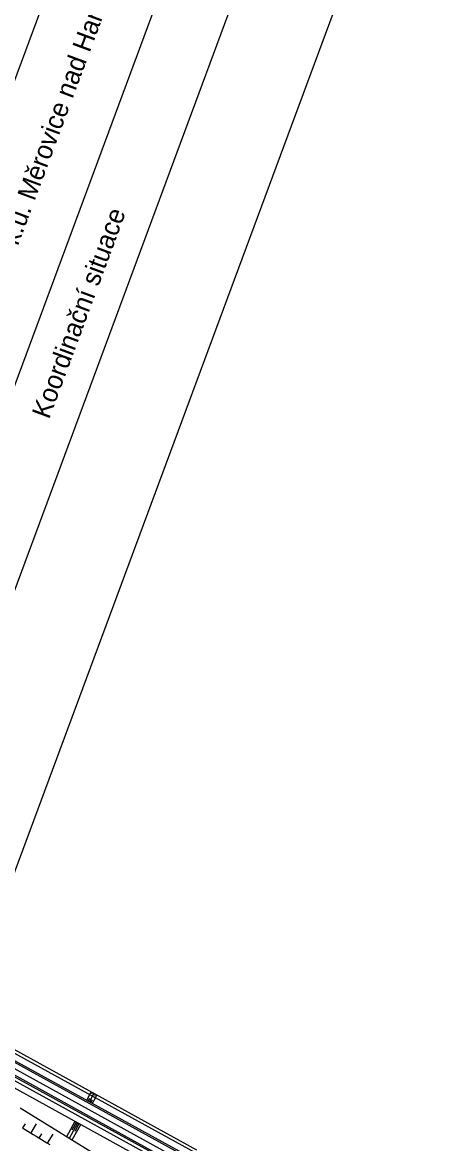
# Model space of a CAD drawing. Extents: x -552278 to -547230, y -1151007 to -1148251.
# Drawn here: x -550305.8 to -550177.8, y -1149028.3 to -1148678 of the extents above; entities that cross this region are included whole.
import ezdxf

# ---------------------------------------------------------------- set-up
doc = ezdxf.new("R2010")
doc.units = 0
for name, color, linetype in [('u_trat navrh', 7, 'Continuous'), ('x_ram1', 7, 'Continuous'), ('x_rozpiska', 7, 'Continuous')]:
    doc.layers.add(name, color=color, linetype=linetype)

msp = doc.modelspace()

# ---------------------------------------------------------------- linework, layer by layer
at = {"layer": 'u_trat navrh'}
for p, q in [((-550461.8, -1148924.01), (-550255.55, -1149037.63)), ((-550461.07, -1148922.69), (-550254.82, -1149036.32)), ((-550460.23, -1148921.16), (-550253.98, -1149034.78)), ((-550462.76, -1148925.76), (-550256.51, -1149039.38)), ((-550441.65, -1148926.54), (-550251.93, -1149031.06)), ((-550442.86, -1148928.73), (-550253.14, -1149033.25)), ((-550442.62, -1148928.29), (-550252.89, -1149032.81)), ((-550371.01, -1148964.32), (-550251.45, -1149030.19)), ((-550285.75, -1149014.72), (-550284.78, -1149012.96)), ((-550285.31, -1149014.96), (-550284.82, -1149014.08)), ((-550284.87, -1149015.2), (-550283.9, -1149013.45)), ((-550284.78, -1149012.96), (-550284.3, -1149012.09)), ((-550284.43, -1149015.44), (-550283.95, -1149014.56)), ((-550284.1, -1149012.77), (-550283.86, -1149012.33)), ((-550283.99, -1149015.68), (-550283.03, -1149013.93)), ((-550283.9, -1149013.45), (-550283.42, -1149012.57)), ((-550283.23, -1149013.25), (-550282.98, -1149012.81)), ((-550283.03, -1149013.93), (-550282.55, -1149013.05)), ((-550306.47, -1149017.11), (-550282.62, -1149031.85)), ((-550305.68, -1149023.37), (-550304.89, -1149022.09)), ((-550303.12, -1149024.95), (-550301.37, -1149022.1)), ((-550291.99, -1149026.06), (-550289.36, -1149021.28)), ((-550291.14, -1149026.58), (-550288.49, -1149021.77)), ((-550290.29, -1149027.11), (-550287.61, -1149022.25)), ((-550290.25, -1149023.92), (-550288.93, -1149021.53)), ((-550289.38, -1149024.43), (-550288.05, -1149022.01)), ((-550300.56, -1149026.52), (-550299.77, -1149025.25)), ((-550298, -1149028.1), (-550296.24, -1149025.27))]:
    msp.add_line(p, q, dxfattribs=at)
for points in [[(-550255.07, -1149036.76), (-550461.31, -1148923.13)], [(-550305.83, -1149023.29), (-550304.97, -1149023.81), (-550304.12, -1149024.33), (-550303.27, -1149024.86), (-550302.41, -1149025.38), (-550301.56, -1149025.91), (-550300.71, -1149026.43), (-550299.86, -1149026.96), (-550299, -1149027.48), (-550298.15, -1149028.01), (-550297.3, -1149028.54)]]:
    msp.add_lwpolyline(points, dxfattribs=at)
at = {"layer": 'x_ram1'}
msp.add_lwpolyline([(-550696.5, -1149991.01), (-550168.47, -1148566.23), (-551020.03, -1148250.64), (-551548.05, -1149675.43)], close=True, dxfattribs=at)
at = {"layer": 'x_rozpiska'}
for p, q in [((-550368.3, -1148858.19), (-550259.6, -1148564.88)), ((-550337.24, -1148869.7), (-550228.54, -1148576.39))]:
    msp.add_line(p, q, dxfattribs=at)
msp.add_lwpolyline([(-550420.06, -1148839), (-550311.36, -1148545.7), (-550207.84, -1148584.06), (-550316.54, -1148877.37)], close=True, dxfattribs=at)

# ---------------------------------------------------------------- texts
for s, p in [('Realizace opatření KoPÚ k.ú. Měrovice nad Hanou', (-550338.69, -1148832.94)), ('Koordinační situace', (-550297.5, -1148802.2))]:
    msp.add_text(s, height=5.888, rotation=69.6654, dxfattribs=at).set_placement(p)

doc.saveas('drawing.dxf')
